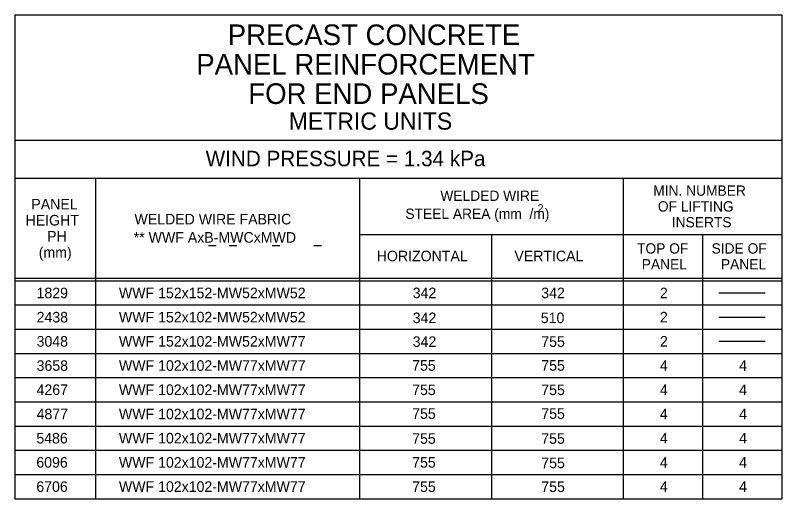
# Model space of a CAD drawing. Extents: x 3385 to 6532, y -616 to 1166.
# Drawn here: x 6308.8 to 6531.9, y 196.3 to 336.9 of the extents above; entities that cross this region are included whole.
import ezdxf

# ---------------------------------------------------------------- set-up
doc = ezdxf.new("R2010")
doc.units = 0
doc.layers.add('1', color=7, linetype='Continuous')

msp = doc.modelspace()

# ---------------------------------------------------------------- linework, layer by layer
at = {"layer": '1'}
for p, q in [((6308.84, 196.33), (6308.84, 336.93)), ((6531.86, 336.93), (6308.84, 336.93)), ((6531.86, 336.93), (6531.86, 196.33)), ((6531.86, 300.5), (6308.84, 300.5)), ((6308.84, 289.52), (6531.86, 289.52)), ((6332.18, 289.52), (6332.18, 196.33)), ((6408.98, 289.52), (6408.98, 196.33)), ((6485.78, 289.52), (6485.78, 196.33)), ((6408.98, 273.19), (6531.86, 273.19)), ((6447.38, 273.19), (6447.38, 196.33)), ((6508.82, 273.19), (6508.82, 196.33)), ((6365.06, 269.95), (6367.29, 269.95)), ((6371.06, 269.95), (6373.29, 269.95)), ((6383.55, 269.95), (6385.78, 269.95)), ((6395.73, 269.95), (6397.96, 269.95)), ((6308.84, 260.46), (6531.86, 260.46)), ((6308.84, 259.71), (6531.86, 259.71)), ((6513.62, 256.19), (6527.06, 256.19)), ((6308.84, 252.67), (6531.86, 252.67)), ((6513.62, 249.15), (6527.06, 249.15)), ((6308.84, 245.63), (6531.86, 245.63)), ((6513.62, 242.11), (6527.06, 242.11)), ((6308.84, 238.59), (6531.86, 238.59)), ((6308.84, 231.55), (6531.86, 231.55)), ((6308.84, 224.5), (6531.86, 224.5)), ((6308.84, 217.46), (6531.86, 217.46)), ((6308.84, 210.42), (6531.86, 210.42)), ((6308.84, 203.38), (6531.86, 203.38)), ((6308.84, 196.33), (6531.86, 196.33))]:
    msp.add_line(p, q, dxfattribs=at)

# ---------------------------------------------------------------- texts
for s, height, p in [('PRECAST CONCRETE', 6.0001, (6370.64, 328.27)), ('PANEL REINFORCEMENT', 6.0001, (6361.5, 319.71)), ('FOR END PANELS', 6.0001, (6376.64, 311.15)), ('METRIC UNITS', 5.0001, (6388.43, 303.67)), ('WIND PRESSURE = 1.34 kPa', 4.5001, (6364.23, 293.03)), ('WELDED WIRE', 3, (6432.53, 282.95)), ('MIN. NUMBER', 3, (6494.48, 284.45)), ('PANEL', 3.072, (6313.5, 280.46)), ('2', 2.3, (6460.85, 279.68)), ('OF LIFTING', 3, (6495.83, 279.85)), ('HEIGHT', 3.072, (6311.81, 275.79)), ('WELDED WIRE FABRIC', 3.072, (6343.51, 276.11)), ('STEEL AREA (mm  /m)', 3, (6422.35, 277.71)), ('INSERTS', 3, (6499.89, 275.25)), ('PH', 3.072, (6318.1, 271.12)), ('** WWF AxB-MWCxMWD', 3.072, (6343.3, 270.8)), ('TOP OF', 3, (6489.77, 267.62)), ('SIDE OF', 3, (6511.46, 267.62)), ('(mm)', 3.072, (6315.66, 266.44)), ('HORIZONTAL', 3.072, (6414.02, 265.39)), ('VERTICAL', 3.072, (6454.08, 265.39)), ('PANEL', 3, (6491.13, 263.02)), ('PANEL', 3, (6514.17, 263.02)), ('1829', 3.072, (6315.03, 254.64)), ('WWF 152x152-MW52xMW52', 3.072, (6338.99, 254.64)), ('342', 3.072, (6424.49, 254.65)), ('342', 3.072, (6461.9, 254.65)), ('2', 3.07, (6496.43, 254.64)), ('2438', 3.072, (6315.04, 247.59)), ('WWF 152x102-MW52xMW52', 3.072, (6338.99, 247.6)), ('342', 3.072, (6424.49, 247.4)), ('510', 3.072, (6461.77, 247.4)), ('2', 3.07, (6496.43, 247.6)), ('3048', 3.072, (6315.04, 240.56)), ('WWF 152x102-MW52xMW77', 3.072, (6338.99, 240.56)), ('342', 3.072, (6424.49, 240.48)), ('755', 3.072, (6461.9, 240.48)), ('2', 3.07, (6496.43, 240.56)), ('3658', 3.072, (6315.04, 233.51)), ('WWF 102x102-MW77xMW77', 3.072, (6338.99, 233.52)), ('755', 3.072, (6424.33, 233.55)), ('755', 3.072, (6461.9, 233.55)), ('4', 3.07, (6496.43, 233.52)), ('4', 3.07, (6519.47, 233.51)), ('4267', 3.072, (6315.03, 226.49)), ('WWF 102x102-MW77xMW77', 3.072, (6338.99, 226.48)), ('755', 3.072, (6424.33, 226.46)), ('755', 3.072, (6461.9, 226.46)), ('4', 3.07, (6496.43, 226.48)), ('4', 3.07, (6519.47, 226.47)), ('4877', 3.072, (6315.04, 219.44)), ('WWF 102x102-MW77xMW77', 3.072, (6338.99, 219.43)), ('755', 3.072, (6424.33, 219.54)), ('755', 3.072, (6461.9, 219.54)), ('4', 3.07, (6496.43, 219.43)), ('4', 3.07, (6519.47, 219.42)), ('5486', 3.072, (6314.96, 212.39)), ('WWF 102x102-MW77xMW77', 3.072, (6338.99, 212.39)), ('755', 3.072, (6424.33, 212.29)), ('755', 3.072, (6461.9, 212.29)), ('4', 3.07, (6496.43, 212.39)), ('4', 3.07, (6519.47, 212.38)), ('6096', 3.072, (6314.96, 205.36)), ('WWF 102x102-MW77xMW77', 3.072, (6338.99, 205.35)), ('755', 3.072, (6424.33, 205.36)), ('755', 3.072, (6461.9, 205.2)), ('4', 3.07, (6496.43, 205.35)), ('4', 3.07, (6519.47, 205.34)), ('6706', 3.072, (6314.96, 198.3)), ('WWF 102x102-MW77xMW77', 3.072, (6338.99, 198.31)), ('755', 3.072, (6424.33, 198.27)), ('755', 3.072, (6461.9, 198.27)), ('4', 3.07, (6496.43, 198.31)), ('4', 3.07, (6519.47, 198.3))]:
    msp.add_text(s, height=height, dxfattribs=at).set_placement(p)

doc.saveas('drawing.dxf')
